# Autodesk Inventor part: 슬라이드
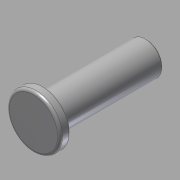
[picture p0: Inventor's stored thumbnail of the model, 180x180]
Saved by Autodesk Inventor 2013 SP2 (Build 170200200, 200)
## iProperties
Company: 한국ATC센터
Created: 2015-11
Part Number: 슬라이드
Document SubType Name: Modeling
Designer: mdu
Density: 7.86 g/cm^3
Material: 강철, 연강
Mass: 53.476 g
Surface Area: 25.6477 cm^2
Volume: 6.80356 cm^3
Author: mdu
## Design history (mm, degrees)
sketch "스케치1"
  geometry: L1 (13.5, 41)-(13.5, 74) reference; L2 (13.5, 74)-(26.5, 74) reference; L3 (20, 74)-(20, 29); L4 (20, 74)-(13.5, 74); L5 (13.5, 74)-(13.5, 33); L6 (13.5, 33)-(9.5, 33); L7 (9.5, 33)-(9.5, 29); L8 (20, 73.5)-(13.5, 73.5); L9 (20, 29)-(9.5, 29); 1 further point
  constraints: 16 end point, 4 perpendicular, 3 point on line, 1 collinear, 1 midpoint, 1 parallel, 1 vertical, 2 other
  dimensions: "d0" = 45 distance of L3.start L3.end; "d1" = 21 diameter of L7 L3; "d2" = 4 distance from line of L3.end L6; "d4" = 0.5 distance between parallel lines of L8 L2
revolve "회전1" sketch "스케치1" stored, may be unused: angle "d5" = 90 deg
fillet "모깎기1" dims "d6" = 1
fillet "모깎기3" dims "d8" = 0.5
chamfer "모따기1" distance "d9" = 0.5; stored, may be unused: second distance "d10" = 2, angle "d11" = 45 deg
sketch "스케치2"
  geometry: C1 r 6.5 at (0, 0) reference; C2 r 7.25 at (0, 0); 1 further point
  constraints: 1 centre point, 1 coincident
  dimensions: "d12" = 14.5 diameter of C2
extrude "돌출1" join sketch "스케치2" distance "d13" = 2; taper "d14" = 0 deg
node "솔리드1"
node "참조1"
